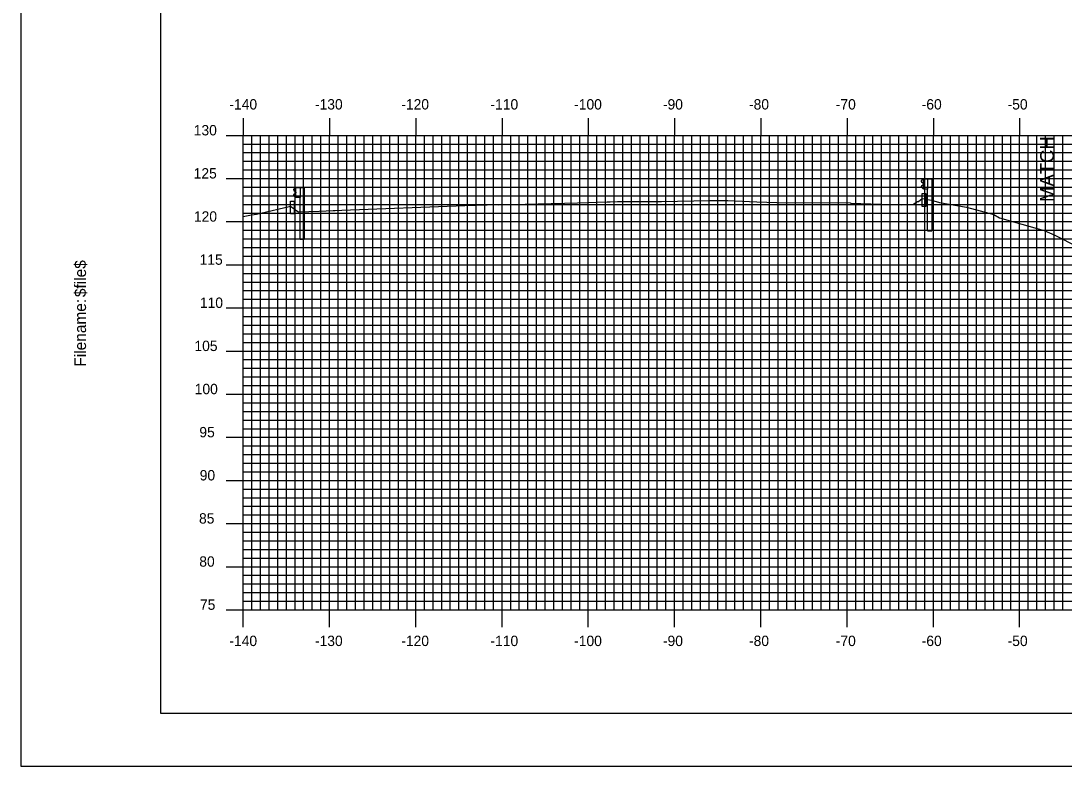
# Model space of a CAD drawing. Extents: x 856871 to 857214, y 364366 to 364586.
# Drawn here: x 856871 to 856992, y 364365.7 to 364452.1 of the extents above; entities that cross this region are included whole.
import ezdxf

# ---------------------------------------------------------------- set-up
doc = ezdxf.new("R2010")
doc.units = 0
for name, color, linetype in [('ANNOTATION', 7, 'Continuous'), ('BORDER', 7, 'Continuous'), ('H_V ANNOTATION', 7, 'Continuous'), ('M_Roadway_Centerline', 7, 'Continuous'), ('MAJOR', 7, 'Continuous'), ('MINOR', 7, 'Continuous'), ('PLOT BOUNDARY', 7, 'Continuous'), ('S_Curb_Type_1', 7, 'Continuous'), ('S_Guardrail_Beam', 7, 'Continuous'), ('S_Roadway_Centerline', 7, 'Continuous')]:
    doc.layers.add(name, color=color, linetype=linetype)

msp = doc.modelspace()

# ---------------------------------------------------------------- linework, layer by layer
at = {"layer": 'BORDER'}
msp.add_lwpolyline([(856887.22, 364371.79), (857207.22, 364371.79), (857207.22, 364581.79), (856887.22, 364581.79)], close=True, dxfattribs=at)
at = {"layer": 'MAJOR'}
for p, q in [((856896.82, 364440.79), (856896.82, 364438.79)), ((856906.82, 364440.79), (856906.82, 364438.79)), ((856916.82, 364440.79), (856916.82, 364438.79)), ((856926.82, 364440.79), (856926.82, 364438.79)), ((856936.82, 364440.79), (856936.82, 364438.79)), ((856946.82, 364440.79), (856946.82, 364438.79)), ((856956.82, 364440.79), (856956.82, 364438.79)), ((856966.82, 364440.79), (856966.82, 364438.79)), ((856976.82, 364440.79), (856976.82, 364438.79)), ((856986.82, 364440.79), (856986.82, 364438.79)), ((856894.82, 364438.79), (856896.82, 364438.79)), ((856896.82, 364438.79), (857176.82, 364438.79)), ((856896.82, 364383.79), (856896.82, 364438.79)), ((856896.82, 364383.79), (856896.82, 364438.79)), ((856896.82, 364438.79), (857176.82, 364438.79)), ((856906.82, 364383.79), (856906.82, 364438.79)), ((856916.82, 364383.79), (856916.82, 364438.79)), ((856926.82, 364383.79), (856926.82, 364438.79)), ((856936.82, 364383.79), (856936.82, 364438.79)), ((856946.82, 364383.79), (856946.82, 364438.79)), ((856956.82, 364383.79), (856956.82, 364438.79)), ((856966.82, 364383.79), (856966.82, 364438.79)), ((856976.82, 364383.79), (856976.82, 364438.79)), ((856986.82, 364383.79), (856986.82, 364438.79)), ((856894.82, 364433.79), (856896.82, 364433.79)), ((856896.82, 364433.79), (857176.82, 364433.79)), ((856894.82, 364428.79), (856896.82, 364428.79)), ((856896.82, 364428.79), (857176.82, 364428.79)), ((856894.82, 364423.79), (856896.82, 364423.79)), ((856896.82, 364423.79), (857176.82, 364423.79)), ((856894.82, 364418.79), (856896.82, 364418.79)), ((856896.82, 364418.79), (857176.82, 364418.79)), ((856894.82, 364413.79), (856896.82, 364413.79)), ((856896.82, 364413.79), (857176.82, 364413.79)), ((856894.82, 364408.79), (856896.82, 364408.79)), ((856896.82, 364408.79), (857176.82, 364408.79)), ((856894.82, 364403.79), (856896.82, 364403.79)), ((856896.82, 364403.79), (857176.82, 364403.79)), ((856894.82, 364398.79), (856896.82, 364398.79)), ((856896.82, 364398.79), (857176.82, 364398.79)), ((856894.82, 364393.79), (856896.82, 364393.79)), ((856896.82, 364393.79), (857176.82, 364393.79)), ((856894.82, 364388.79), (856896.82, 364388.79)), ((856896.82, 364388.79), (857176.82, 364388.79)), ((856894.82, 364383.79), (856896.82, 364383.79)), ((856896.82, 364383.79), (857176.82, 364383.79)), ((856896.82, 364383.79), (857176.82, 364383.79)), ((856896.82, 364381.78), (856896.82, 364383.79)), ((856906.82, 364381.78), (856906.82, 364383.79)), ((856916.82, 364381.78), (856916.82, 364383.79)), ((856926.82, 364381.78), (856926.82, 364383.79)), ((856936.82, 364381.78), (856936.82, 364383.79)), ((856946.82, 364381.78), (856946.82, 364383.79)), ((856956.82, 364381.78), (856956.82, 364383.79)), ((856966.82, 364381.78), (856966.82, 364383.79)), ((856976.82, 364381.78), (856976.82, 364383.79)), ((856986.82, 364381.78), (856986.82, 364383.79))]:
    msp.add_line(p, q, dxfattribs=at)
at = {"layer": 'MINOR'}
for p, q in [((856896.82, 364437.79), (857176.82, 364437.79)), ((856896.82, 364437.79), (856898.83, 364437.79)), ((856897.82, 364383.79), (856897.82, 364438.79)), ((856898.82, 364383.79), (856898.82, 364438.79)), ((856899.82, 364383.79), (856899.82, 364438.79)), ((856900.82, 364383.79), (856900.82, 364438.79)), ((856901.82, 364383.79), (856901.82, 364438.79)), ((856902.82, 364383.79), (856902.82, 364438.79)), ((856903.82, 364383.79), (856903.82, 364438.79)), ((856904.82, 364383.79), (856904.82, 364438.79)), ((856905.82, 364383.79), (856905.82, 364438.79)), ((856907.82, 364383.79), (856907.82, 364438.79)), ((856908.82, 364383.79), (856908.82, 364438.79)), ((856909.82, 364383.79), (856909.82, 364438.79)), ((856910.82, 364383.79), (856910.82, 364438.79)), ((856911.82, 364383.79), (856911.82, 364438.79)), ((856912.82, 364383.79), (856912.82, 364438.79)), ((856913.82, 364383.79), (856913.82, 364438.79)), ((856914.82, 364383.79), (856914.82, 364438.79)), ((856915.82, 364383.79), (856915.82, 364438.79)), ((856917.82, 364383.79), (856917.82, 364438.79)), ((856918.82, 364383.79), (856918.82, 364438.79)), ((856919.82, 364383.79), (856919.82, 364438.79)), ((856920.82, 364383.79), (856920.82, 364438.79)), ((856921.82, 364383.79), (856921.82, 364438.79)), ((856922.82, 364383.79), (856922.82, 364438.79)), ((856923.82, 364383.79), (856923.82, 364438.79)), ((856924.82, 364383.79), (856924.82, 364438.79)), ((856925.82, 364383.79), (856925.82, 364438.79)), ((856927.82, 364383.79), (856927.82, 364438.79)), ((856928.82, 364383.79), (856928.82, 364438.79)), ((856929.82, 364383.79), (856929.82, 364438.79)), ((856930.82, 364383.79), (856930.82, 364438.79)), ((856931.82, 364383.79), (856931.82, 364438.79)), ((856932.82, 364383.79), (856932.82, 364438.79)), ((856933.82, 364383.79), (856933.82, 364438.79)), ((856934.82, 364383.79), (856934.82, 364438.79)), ((856935.82, 364383.79), (856935.82, 364438.79)), ((856937.82, 364383.79), (856937.82, 364438.79)), ((856938.82, 364383.79), (856938.82, 364438.79)), ((856939.82, 364383.79), (856939.82, 364438.79)), ((856940.82, 364383.79), (856940.82, 364438.79)), ((856941.82, 364383.79), (856941.82, 364438.79)), ((856942.82, 364383.79), (856942.82, 364438.79)), ((856943.82, 364383.79), (856943.82, 364438.79)), ((856944.82, 364383.79), (856944.82, 364438.79)), ((856945.82, 364383.79), (856945.82, 364438.79)), ((856947.82, 364383.79), (856947.82, 364438.79)), ((856948.82, 364383.79), (856948.82, 364438.79)), ((856949.82, 364383.79), (856949.82, 364438.79)), ((856950.82, 364383.79), (856950.82, 364438.79)), ((856951.82, 364383.79), (856951.82, 364438.79)), ((856952.82, 364383.79), (856952.82, 364438.79)), ((856953.82, 364383.79), (856953.82, 364438.79)), ((856954.82, 364383.79), (856954.82, 364438.79)), ((856955.82, 364383.79), (856955.82, 364438.79)), ((856957.82, 364383.79), (856957.82, 364438.79)), ((856958.82, 364383.79), (856958.82, 364438.79)), ((856959.82, 364383.79), (856959.82, 364438.79)), ((856960.82, 364383.79), (856960.82, 364438.79)), ((856961.82, 364383.79), (856961.82, 364438.79)), ((856962.82, 364383.79), (856962.82, 364438.79)), ((856963.82, 364383.79), (856963.82, 364438.79)), ((856964.82, 364383.79), (856964.82, 364438.79)), ((856965.82, 364383.79), (856965.82, 364438.79)), ((856967.82, 364383.79), (856967.82, 364438.79)), ((856968.82, 364383.79), (856968.82, 364438.79)), ((856969.82, 364383.79), (856969.82, 364438.79)), ((856970.82, 364383.79), (856970.82, 364438.79)), ((856971.82, 364383.79), (856971.82, 364438.79)), ((856972.82, 364383.79), (856972.82, 364438.79)), ((856973.82, 364383.79), (856973.82, 364438.79)), ((856974.82, 364383.79), (856974.82, 364438.79)), ((856975.82, 364383.79), (856975.82, 364438.79)), ((856977.82, 364383.79), (856977.82, 364438.79)), ((856978.82, 364383.79), (856978.82, 364438.79)), ((856979.82, 364383.79), (856979.82, 364438.79)), ((856980.82, 364383.79), (856980.82, 364438.79)), ((856981.82, 364383.79), (856981.82, 364438.79)), ((856982.82, 364383.79), (856982.82, 364438.79)), ((856983.82, 364383.79), (856983.82, 364438.79)), ((856984.82, 364383.79), (856984.82, 364438.79)), ((856985.82, 364383.79), (856985.82, 364438.79)), ((856987.82, 364383.79), (856987.82, 364438.79)), ((856988.82, 364383.79), (856988.82, 364438.79)), ((856989.82, 364383.79), (856989.82, 364438.79)), ((856990.82, 364383.79), (856990.82, 364438.79)), ((856991.82, 364383.79), (856991.82, 364438.79)), ((856896.82, 364436.79), (857176.82, 364436.79)), ((856896.82, 364436.79), (856898.83, 364436.79)), ((856896.82, 364435.79), (857176.82, 364435.79)), ((856896.82, 364435.79), (856898.83, 364435.79)), ((856896.82, 364434.79), (857176.82, 364434.79)), ((856896.82, 364434.79), (856898.83, 364434.79)), ((856896.82, 364432.79), (857176.82, 364432.79)), ((856896.82, 364432.79), (856898.83, 364432.79)), ((856896.82, 364431.79), (857176.82, 364431.79)), ((856896.82, 364431.79), (856898.83, 364431.79)), ((856896.82, 364430.79), (857176.82, 364430.79)), ((856896.82, 364430.79), (856898.83, 364430.79)), ((856896.82, 364429.79), (857176.82, 364429.79)), ((856896.82, 364429.79), (856898.83, 364429.79)), ((856896.82, 364427.79), (857176.82, 364427.79)), ((856896.82, 364427.79), (856898.83, 364427.79)), ((856896.82, 364426.79), (857176.82, 364426.79)), ((856896.82, 364426.79), (856898.83, 364426.79)), ((856896.82, 364425.79), (857176.82, 364425.79)), ((856896.82, 364425.79), (856898.83, 364425.79)), ((856896.82, 364424.79), (857176.82, 364424.79)), ((856896.82, 364424.79), (856898.83, 364424.79)), ((856896.82, 364422.79), (857176.82, 364422.79)), ((856896.82, 364422.79), (856898.83, 364422.79)), ((856896.82, 364421.79), (857176.82, 364421.79)), ((856896.82, 364421.79), (856898.83, 364421.79)), ((856896.82, 364420.79), (857176.82, 364420.79)), ((856896.82, 364420.79), (856898.83, 364420.79)), ((856896.82, 364419.79), (857176.82, 364419.79)), ((856896.82, 364419.79), (856898.83, 364419.79)), ((856896.82, 364417.79), (857176.82, 364417.79)), ((856896.82, 364417.79), (856898.83, 364417.79)), ((856896.82, 364416.79), (857176.82, 364416.79)), ((856896.82, 364416.79), (856898.83, 364416.79)), ((856896.82, 364415.79), (857176.82, 364415.79)), ((856896.82, 364415.79), (856898.83, 364415.79)), ((856896.82, 364414.79), (857176.82, 364414.79)), ((856896.82, 364414.79), (856898.83, 364414.79)), ((856896.82, 364412.79), (857176.82, 364412.79)), ((856896.82, 364412.79), (856898.83, 364412.79)), ((856896.82, 364411.79), (857176.82, 364411.79)), ((856896.82, 364411.79), (856898.83, 364411.79)), ((856896.82, 364410.79), (857176.82, 364410.79)), ((856896.82, 364410.79), (856898.83, 364410.79)), ((856896.82, 364409.79), (857176.82, 364409.79)), ((856896.82, 364409.79), (856898.83, 364409.79)), ((856896.82, 364407.79), (857176.82, 364407.79)), ((856896.82, 364407.79), (856898.83, 364407.79)), ((856896.82, 364406.79), (857176.82, 364406.79)), ((856896.82, 364406.79), (856898.83, 364406.79)), ((856896.82, 364405.79), (857176.82, 364405.79)), ((856896.82, 364405.79), (856898.83, 364405.79)), ((856896.82, 364404.79), (857176.82, 364404.79)), ((856896.82, 364404.79), (856898.83, 364404.79)), ((856896.82, 364402.79), (857176.82, 364402.79)), ((856896.82, 364402.79), (856898.83, 364402.79)), ((856896.82, 364401.79), (857176.82, 364401.79)), ((856896.82, 364401.79), (856898.83, 364401.79)), ((856896.82, 364400.79), (857176.82, 364400.79)), ((856896.82, 364400.79), (856898.83, 364400.79)), ((856896.82, 364399.79), (857176.82, 364399.79)), ((856896.82, 364399.79), (856898.83, 364399.79)), ((856896.82, 364397.79), (857176.82, 364397.79)), ((856896.82, 364397.79), (856898.83, 364397.79)), ((856896.82, 364396.79), (857176.82, 364396.79)), ((856896.82, 364396.79), (856898.83, 364396.79)), ((856896.82, 364395.79), (857176.82, 364395.79)), ((856896.82, 364395.79), (856898.83, 364395.79)), ((856896.82, 364394.79), (857176.82, 364394.79)), ((856896.82, 364394.79), (856898.83, 364394.79)), ((856896.82, 364392.79), (857176.82, 364392.79)), ((856896.82, 364392.79), (856898.83, 364392.79)), ((856896.82, 364391.79), (857176.82, 364391.79)), ((856896.82, 364391.79), (856898.83, 364391.79)), ((856896.82, 364390.79), (857176.82, 364390.79)), ((856896.82, 364390.79), (856898.83, 364390.79)), ((856896.82, 364389.79), (857176.82, 364389.79)), ((856896.82, 364389.79), (856898.83, 364389.79)), ((856896.82, 364387.79), (857176.82, 364387.79)), ((856896.82, 364387.79), (856898.83, 364387.79)), ((856896.82, 364386.79), (857176.82, 364386.79)), ((856896.82, 364386.79), (856898.83, 364386.79)), ((856896.82, 364385.79), (857176.82, 364385.79)), ((856896.82, 364385.79), (856898.83, 364385.79)), ((856896.82, 364384.79), (857176.82, 364384.79)), ((856896.82, 364384.79), (856898.83, 364384.79))]:
    msp.add_line(p, q, dxfattribs=at)
at = {"layer": 'PLOT BOUNDARY'}
msp.add_lwpolyline([(856871.04, 364365.67), (857211.04, 364365.67), (857211.04, 364585.67), (856871.04, 364585.67)], close=True, dxfattribs=at)
at = {"layer": 'S_Curb_Type_1'}
for points in [[(856975.53, 364432.04), (856975.95, 364432.04), (856975.95, 364430.54), (856975.53, 364430.54)], [(856975.53, 364432.04), (856975.95, 364432.04), (856975.95, 364430.54), (856975.53, 364430.54)], [(856902.29, 364431.18), (856902.71, 364431.18), (856902.71, 364429.68), (856902.29, 364429.68)], [(856902.29, 364431.18), (856902.71, 364431.18), (856902.71, 364429.68), (856902.29, 364429.68)]]:
    msp.add_lwpolyline(points, close=True, dxfattribs=at)
at = {"layer": 'S_Guardrail_Beam'}
for p, q in [((856975.58, 364433.65), (856975.43, 364433.55)), ((856975.58, 364433.65), (856975.43, 364433.55)), ((856975.43, 364433.4), (856975.63, 364433.27)), ((856975.43, 364433.4), (856975.63, 364433.27)), ((856975.63, 364433.05), (856975.43, 364432.91)), ((856975.63, 364433.05), (856975.43, 364432.91)), ((856975.68, 364433.67), (856975.59, 364433.65)), ((856975.68, 364433.67), (856975.59, 364433.65)), ((856975.66, 364433.2), (856975.66, 364433.11)), ((856975.66, 364433.2), (856975.66, 364433.11)), ((856975.68, 364433.74), (856976.16, 364433.74)), ((856975.68, 364432.57), (856975.68, 364433.74)), ((856975.68, 364433.74), (856976.16, 364433.74)), ((856975.68, 364432.57), (856975.68, 364433.74)), ((856976.16, 364433.74), (856976.66, 364433.74)), ((856976.16, 364433.74), (856976.16, 364432.57)), ((856976.16, 364433.74), (856976.66, 364433.74)), ((856976.16, 364433.74), (856976.16, 364432.57)), ((856976.66, 364433.74), (856976.66, 364427.74)), ((856976.66, 364433.74), (856976.66, 364427.74)), ((856902.81, 364432.67), (856902.67, 364432.57)), ((856902.81, 364432.67), (856902.67, 364432.57)), ((856902.67, 364432.42), (856902.86, 364432.29)), ((856902.67, 364432.42), (856902.86, 364432.29)), ((856902.86, 364432.07), (856902.67, 364431.93)), ((856902.86, 364432.07), (856902.67, 364431.93)), ((856902.67, 364431.79), (856902.81, 364431.69)), ((856902.67, 364431.79), (856902.81, 364431.69)), ((856902.91, 364432.69), (856902.83, 364432.67)), ((856902.91, 364432.69), (856902.83, 364432.67)), ((856902.83, 364431.68), (856902.91, 364431.67)), ((856902.83, 364431.68), (856902.91, 364431.67)), ((856902.9, 364432.22), (856902.9, 364432.13)), ((856902.9, 364432.22), (856902.9, 364432.13)), ((856902.91, 364432.76), (856903.4, 364432.76)), ((856902.91, 364431.59), (856902.91, 364432.76)), ((856902.91, 364432.76), (856903.4, 364432.76)), ((856902.91, 364431.59), (856902.91, 364432.76)), ((856903.4, 364432.76), (856903.89, 364432.76)), ((856903.4, 364432.76), (856903.4, 364431.59)), ((856903.4, 364432.76), (856903.89, 364432.76)), ((856903.4, 364432.76), (856903.4, 364431.59)), ((856903.89, 364432.76), (856903.89, 364426.76)), ((856903.89, 364432.76), (856903.89, 364426.76)), ((856975.43, 364432.77), (856975.58, 364432.67)), ((856975.43, 364432.77), (856975.58, 364432.67)), ((856975.59, 364432.66), (856975.68, 364432.65)), ((856975.59, 364432.66), (856975.68, 364432.65)), ((856976.16, 364432.57), (856975.68, 364432.57)), ((856976.16, 364432.57), (856975.68, 364432.57)), ((856976.16, 364427.74), (856976.16, 364432.57)), ((856976.16, 364427.74), (856976.16, 364432.57)), ((856903.4, 364431.59), (856902.91, 364431.59)), ((856903.4, 364431.59), (856902.91, 364431.59)), ((856903.4, 364426.76), (856903.4, 364431.59)), ((856903.4, 364426.76), (856903.4, 364431.59)), ((856976.16, 364427.74), (856976.66, 364427.74)), ((856976.16, 364427.74), (856976.66, 364427.74)), ((856903.4, 364426.76), (856903.89, 364426.76)), ((856903.4, 364426.76), (856903.89, 364426.76))]:
    msp.add_line(p, q, dxfattribs=at)
for centre, major_axis, start_param, end_param in [((856975.48, 364433.48), (-0.0877, 0), 5.323254, 7.243116), ((856975.48, 364433.48), (-0.0877, 0), 5.323254, 7.243116), ((856975.48, 364432.84), (-0.0877, 0), 5.323254, 7.243116), ((856975.48, 364432.84), (-0.0877, 0), 5.323254, 7.243116), ((856975.6, 364433.61), (-0.0417, 0), 4.886922, 5.323254), ((856975.6, 364433.61), (-0.0417, 0), 4.886922, 5.323254), ((856975.58, 364433.2), (0.0789, 0), 0, 0.959931), ((856975.58, 364433.2), (0.0789, 0), 0, 0.959931), ((856975.58, 364433.11), (0.0789, 0), 5.323254, 6.283185), ((856975.58, 364433.11), (0.0789, 0), 5.323254, 6.283185), ((856902.72, 364432.5), (-0.0877, 0), 5.323254, 7.243116), ((856902.72, 364432.5), (-0.0877, 0), 5.323254, 7.243116), ((856902.72, 364431.86), (-0.0877, 0), 5.323254, 7.243116), ((856902.72, 364431.86), (-0.0877, 0), 5.323254, 7.243116), ((856902.83, 364432.63), (-0.0417, 0), 4.886922, 5.323254), ((856902.83, 364432.63), (-0.0417, 0), 4.886922, 5.323254), ((856902.83, 364431.72), (-0.0417, 0), 0.959931, 1.396263), ((856902.83, 364431.72), (-0.0417, 0), 0.959931, 1.396263), ((856902.82, 364432.22), (0.0789, 0), 0, 0.959931), ((856902.82, 364432.22), (0.0789, 0), 0, 0.959931), ((856902.82, 364432.13), (0.0789, 0), 5.323254, 6.283185), ((856902.82, 364432.13), (0.0789, 0), 5.323254, 6.283185), ((856975.6, 364432.7), (-0.0417, 0), 0.959931, 1.396263), ((856975.6, 364432.7), (-0.0417, 0), 0.959931, 1.396263)]:
    msp.add_ellipse(centre, major_axis=major_axis, ratio=0.995501, start_param=start_param, end_param=end_param, dxfattribs=at)
at = {"layer": 'S_Roadway_Centerline'}
msp.add_lwpolyline([(856896.82, 364429.38), (856897.57, 364429.54), (856898.35, 364429.66), (856898.69, 364429.74), (856902.29, 364430.59), (856903.13, 364429.96), (856903.17, 364429.93), (856903.21, 364429.92), (856905.62, 364430.01), (856907.23, 364430.07), (856907.48, 364430.08), (856908.26, 364430.11), (856922.5, 364430.65), (856925.11, 364430.75), (856925.48, 364430.76), (856925.89, 364430.77), (856926.44, 364430.72), (856935.58, 364430.96), (856938.99, 364431.08), (856939.34, 364431.1), (856940.2, 364431.11), (856940.71, 364431.12), (856943.16, 364431.14), (856945.3, 364431.14), (856950.9, 364431.24), (856952.72, 364431.24), (856952.98, 364431.25), (856956.36, 364431.08), (856958.66, 364431), (856967.2, 364430.99), (856967.23, 364430.92), (856973.12, 364430.74), (856973.14, 364430.74), (856974.46, 364430.79), (856974.98, 364431.13), (856975.08, 364431.14), (856975.53, 364431.46), (856976.6, 364431.27), (856977.53, 364431.02), (856980.68, 364430.46), (856983.82, 364429.63), (856984.5, 364429.25), (856989.65, 364427.78), (856990.89, 364427.22), (857004.48, 364420.33)], dxfattribs=at)

# ---------------------------------------------------------------- texts
at = {"layer": 'ANNOTATION'}
msp.add_text('MATCH', height=1.6, rotation=90, dxfattribs=at).set_placement((856990.8, 364431.08))
at = {"layer": 'BORDER'}
for s, p in [('$file$', (856878.59, 364420.04)), ('Filename:', (856878.59, 364411.98))]:
    msp.add_text(s, height=1.339, rotation=90, dxfattribs=at).set_placement(p)
at = {"layer": 'H_V ANNOTATION'}
for s, p in [('-140', (856895.21, 364441.79)), ('-130', (856905.13, 364441.79)), ('-120', (856915.14, 364441.79)), ('-110', (856925.48, 364441.79)), ('-100', (856935.18, 364441.79)), ('-90', (856945.47, 364441.79)), ('-80', (856955.45, 364441.79)), ('-70', (856965.51, 364441.79)), ('-60', (856975.47, 364441.79)), ('-50', (856985.43, 364441.79)), ('130', (856891.08, 364438.79)), ('125', (856891.07, 364433.79)), ('120', (856891.1, 364428.79)), ('115', (856891.76, 364423.79)), ('110', (856891.79, 364418.79)), ('105', (856891.16, 364413.79)), ('100', (856891.19, 364408.79)), ('95', (856891.73, 364403.79)), ('90', (856891.77, 364398.79)), ('85', (856891.69, 364393.79)), ('80', (856891.72, 364388.79)), ('75', (856891.8, 364383.79)), ('-140', (856895.21, 364379.59)), ('-130', (856905.13, 364379.59)), ('-120', (856915.14, 364379.59)), ('-110', (856925.48, 364379.59)), ('-100', (856935.18, 364379.59)), ('-90', (856945.47, 364379.59)), ('-80', (856955.45, 364379.59)), ('-70', (856965.51, 364379.59)), ('-60', (856975.47, 364379.59)), ('-50', (856985.43, 364379.59))]:
    msp.add_text(s, height=1.2, dxfattribs=at).set_placement(p)
at = {"layer": 'M_Roadway_Centerline'}
for s, p in [('C', (856945.29, 364431.14)), ('L', (856945.3, 364431.13))]:
    msp.add_text(s, height=0.0146, dxfattribs=at).set_placement(p)
at = {"layer": 'MAJOR'}
msp.add_text('-', height=0.012, dxfattribs=at).set_placement((856896.81, 364383.79))

doc.saveas('drawing.dxf')
